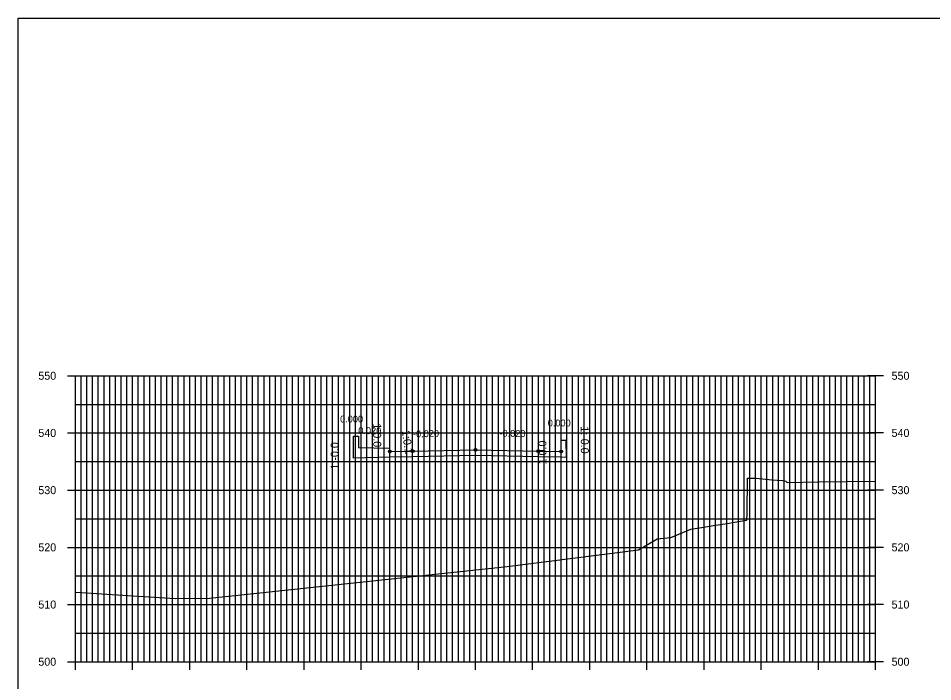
# Model space of a CAD drawing. Extents: x 1509063 to 1512863, y 401160 to 402918.
# Drawn here: x 1511102.7 to 1511262.7, y 402346.1 to 402462.1 of the extents above; entities that cross this region are included whole.
import ezdxf

# ---------------------------------------------------------------- set-up
doc = ezdxf.new("R2010")
doc.units = 0
for name, color, linetype in [('NBL1', 7, 'Continuous'), ('PET_P', 7, 'Continuous'), ('PRC', 7, 'Continuous'), ('PSP_P', 7, 'Continuous'), ('XAX_P', 7, 'Continuous'), ('XAXTIC_P', 7, 'Continuous'), ('XAXTXT_P_T', 7, 'Continuous'), ('XGL_P', 7, 'Continuous'), ('XSL1_P', 7, 'Continuous'), ('XSL1_P_T', 7, 'Continuous'), ('XSL3_P', 7, 'Continuous'), ('XSLOG', 7, 'Continuous')]:
    doc.layers.add(name, color=color, linetype=linetype)

msp = doc.modelspace()

# ---------------------------------------------------------------- linework, layer by layer
at = {"layer": 'NBL1'}
msp.add_lwpolyline([(1511422.73, 402252.08), (1511102.73, 402252.08), (1511102.73, 402462.08), (1511422.73, 402462.08)], close=True, dxfattribs=at)
at = {"layer": 'PET_P'}
for centre in [(1511171.73, 402386.4), (1511193.73, 402386.4)]:
    msp.add_circle(centre, 0.25, dxfattribs=at)
at = {"layer": 'PRC'}
msp.add_circle((1511182.73, 402386.62), 0.25, dxfattribs=at)
at = {"layer": 'PSP_P'}
for centre in [(1511167.73, 402386.32), (1511197.73, 402386.32)]:
    msp.add_circle(centre, 0.25, dxfattribs=at)
at = {"layer": 'XAX_P'}
for p, q in [((1511112.73, 402349.58), (1511112.73, 402399.58)), ((1511182.73, 402349.58), (1511182.73, 402399.58)), ((1511252.73, 402349.58), (1511252.73, 402399.58)), ((1511112.73, 402349.58), (1511252.73, 402349.58))]:
    msp.add_line(p, q, dxfattribs=at)
at = {"layer": 'XAXTIC_P'}
for p, q in [((1511111.33, 402399.58), (1511114.13, 402399.58)), ((1511181.33, 402399.58), (1511184.13, 402399.58)), ((1511254.13, 402399.58), (1511251.33, 402399.58)), ((1511111.33, 402389.58), (1511114.13, 402389.58)), ((1511181.33, 402389.58), (1511184.13, 402389.58)), ((1511254.13, 402389.58), (1511251.33, 402389.58)), ((1511111.33, 402379.58), (1511114.13, 402379.58)), ((1511181.33, 402379.58), (1511184.13, 402379.58)), ((1511254.13, 402379.58), (1511251.33, 402379.58)), ((1511111.33, 402369.58), (1511114.13, 402369.58)), ((1511181.33, 402369.58), (1511184.13, 402369.58)), ((1511254.13, 402369.58), (1511251.33, 402369.58)), ((1511111.33, 402359.58), (1511114.13, 402359.58)), ((1511181.33, 402359.58), (1511184.13, 402359.58)), ((1511254.13, 402359.58), (1511251.33, 402359.58)), ((1511112.73, 402348.18), (1511112.73, 402350.98)), ((1511122.73, 402348.18), (1511122.73, 402350.98)), ((1511132.73, 402348.18), (1511132.73, 402350.98)), ((1511142.73, 402348.18), (1511142.73, 402350.98)), ((1511152.73, 402348.18), (1511152.73, 402350.98)), ((1511162.73, 402348.18), (1511162.73, 402350.98)), ((1511172.73, 402348.18), (1511172.73, 402350.98)), ((1511182.73, 402348.18), (1511182.73, 402350.98)), ((1511192.73, 402348.18), (1511192.73, 402350.98)), ((1511202.73, 402348.18), (1511202.73, 402350.98)), ((1511212.73, 402348.18), (1511212.73, 402350.98)), ((1511222.73, 402348.18), (1511222.73, 402350.98)), ((1511232.73, 402348.18), (1511232.73, 402350.98)), ((1511242.73, 402348.18), (1511242.73, 402350.98)), ((1511252.73, 402348.18), (1511252.73, 402350.98)), ((1511111.33, 402349.58), (1511114.13, 402349.58)), ((1511181.33, 402349.58), (1511184.13, 402349.58)), ((1511254.13, 402349.58), (1511251.33, 402349.58))]:
    msp.add_line(p, q, dxfattribs=at)
at = {"layer": 'XGL_P'}
for p, q in [((1511112.73, 402399.58), (1511252.73, 402399.58)), ((1511112.73, 402349.58), (1511112.73, 402399.58)), ((1511113.73, 402349.58), (1511113.73, 402399.58)), ((1511114.73, 402349.58), (1511114.73, 402399.58)), ((1511115.73, 402349.58), (1511115.73, 402399.58)), ((1511116.73, 402349.58), (1511116.73, 402399.58)), ((1511117.73, 402349.58), (1511117.73, 402399.58)), ((1511118.73, 402349.58), (1511118.73, 402399.58)), ((1511119.73, 402349.58), (1511119.73, 402399.58)), ((1511120.73, 402349.58), (1511120.73, 402399.58)), ((1511121.73, 402349.58), (1511121.73, 402399.58)), ((1511122.73, 402349.58), (1511122.73, 402399.58)), ((1511123.73, 402349.58), (1511123.73, 402399.58)), ((1511124.73, 402349.58), (1511124.73, 402399.58)), ((1511125.73, 402349.58), (1511125.73, 402399.58)), ((1511126.73, 402349.58), (1511126.73, 402399.58)), ((1511127.73, 402349.58), (1511127.73, 402399.58)), ((1511128.73, 402349.58), (1511128.73, 402399.58)), ((1511129.73, 402349.58), (1511129.73, 402399.58)), ((1511130.73, 402349.58), (1511130.73, 402399.58)), ((1511131.73, 402349.58), (1511131.73, 402399.58)), ((1511132.73, 402349.58), (1511132.73, 402399.58)), ((1511133.73, 402349.58), (1511133.73, 402399.58)), ((1511134.73, 402349.58), (1511134.73, 402399.58)), ((1511135.73, 402349.58), (1511135.73, 402399.58)), ((1511136.73, 402349.58), (1511136.73, 402399.58)), ((1511137.73, 402349.58), (1511137.73, 402399.58)), ((1511138.73, 402349.58), (1511138.73, 402399.58)), ((1511139.73, 402349.58), (1511139.73, 402399.58)), ((1511140.73, 402349.58), (1511140.73, 402399.58)), ((1511141.73, 402349.58), (1511141.73, 402399.58)), ((1511142.73, 402349.58), (1511142.73, 402399.58)), ((1511143.73, 402349.58), (1511143.73, 402399.58)), ((1511144.73, 402349.58), (1511144.73, 402399.58)), ((1511145.73, 402349.58), (1511145.73, 402399.58)), ((1511146.73, 402349.58), (1511146.73, 402399.58)), ((1511147.73, 402349.58), (1511147.73, 402399.58)), ((1511148.73, 402349.58), (1511148.73, 402399.58)), ((1511149.73, 402349.58), (1511149.73, 402399.58)), ((1511150.73, 402349.58), (1511150.73, 402399.58)), ((1511151.73, 402349.58), (1511151.73, 402399.58)), ((1511152.73, 402349.58), (1511152.73, 402399.58)), ((1511153.73, 402349.58), (1511153.73, 402399.58)), ((1511154.73, 402349.58), (1511154.73, 402399.58)), ((1511155.73, 402349.58), (1511155.73, 402399.58)), ((1511156.73, 402349.58), (1511156.73, 402399.58)), ((1511157.73, 402349.58), (1511157.73, 402399.58)), ((1511158.73, 402349.58), (1511158.73, 402399.58)), ((1511159.73, 402349.58), (1511159.73, 402399.58)), ((1511160.73, 402349.58), (1511160.73, 402399.58)), ((1511161.73, 402349.58), (1511161.73, 402399.58)), ((1511162.73, 402349.58), (1511162.73, 402399.58)), ((1511163.73, 402349.58), (1511163.73, 402399.58)), ((1511164.73, 402349.58), (1511164.73, 402399.58)), ((1511165.73, 402349.58), (1511165.73, 402399.58)), ((1511166.73, 402349.58), (1511166.73, 402399.58)), ((1511167.73, 402349.58), (1511167.73, 402399.58)), ((1511168.73, 402349.58), (1511168.73, 402399.58)), ((1511169.73, 402349.58), (1511169.73, 402399.58)), ((1511170.73, 402349.58), (1511170.73, 402399.58)), ((1511171.73, 402349.58), (1511171.73, 402399.58)), ((1511172.73, 402349.58), (1511172.73, 402399.58)), ((1511173.73, 402349.58), (1511173.73, 402399.58)), ((1511174.73, 402349.58), (1511174.73, 402399.58)), ((1511175.73, 402349.58), (1511175.73, 402399.58)), ((1511176.73, 402349.58), (1511176.73, 402399.58)), ((1511177.73, 402349.58), (1511177.73, 402399.58)), ((1511178.73, 402349.58), (1511178.73, 402399.58)), ((1511179.73, 402349.58), (1511179.73, 402399.58)), ((1511180.73, 402349.58), (1511180.73, 402399.58)), ((1511181.73, 402349.58), (1511181.73, 402399.58)), ((1511182.73, 402349.58), (1511182.73, 402399.58)), ((1511183.73, 402349.58), (1511183.73, 402399.58)), ((1511184.73, 402349.58), (1511184.73, 402399.58)), ((1511185.73, 402349.58), (1511185.73, 402399.58)), ((1511186.73, 402349.58), (1511186.73, 402399.58)), ((1511187.73, 402349.58), (1511187.73, 402399.58)), ((1511188.73, 402349.58), (1511188.73, 402399.58)), ((1511189.73, 402349.58), (1511189.73, 402399.58)), ((1511190.73, 402349.58), (1511190.73, 402399.58)), ((1511191.73, 402349.58), (1511191.73, 402399.58)), ((1511192.73, 402349.58), (1511192.73, 402399.58)), ((1511193.73, 402349.58), (1511193.73, 402399.58)), ((1511194.73, 402349.58), (1511194.73, 402399.58)), ((1511195.73, 402349.58), (1511195.73, 402399.58)), ((1511196.73, 402349.58), (1511196.73, 402399.58)), ((1511197.73, 402349.58), (1511197.73, 402399.58)), ((1511198.73, 402349.58), (1511198.73, 402399.58)), ((1511199.73, 402349.58), (1511199.73, 402399.58)), ((1511200.73, 402349.58), (1511200.73, 402399.58)), ((1511201.73, 402349.58), (1511201.73, 402399.58)), ((1511202.73, 402349.58), (1511202.73, 402399.58)), ((1511203.73, 402349.58), (1511203.73, 402399.58)), ((1511204.73, 402349.58), (1511204.73, 402399.58)), ((1511205.73, 402349.58), (1511205.73, 402399.58)), ((1511206.73, 402349.58), (1511206.73, 402399.58)), ((1511207.73, 402349.58), (1511207.73, 402399.58)), ((1511208.73, 402349.58), (1511208.73, 402399.58)), ((1511209.73, 402349.58), (1511209.73, 402399.58)), ((1511210.73, 402349.58), (1511210.73, 402399.58)), ((1511211.73, 402349.58), (1511211.73, 402399.58)), ((1511212.73, 402349.58), (1511212.73, 402399.58)), ((1511213.73, 402349.58), (1511213.73, 402399.58)), ((1511214.73, 402349.58), (1511214.73, 402399.58)), ((1511215.73, 402349.58), (1511215.73, 402399.58)), ((1511216.73, 402349.58), (1511216.73, 402399.58)), ((1511217.73, 402349.58), (1511217.73, 402399.58)), ((1511218.73, 402349.58), (1511218.73, 402399.58)), ((1511219.73, 402349.58), (1511219.73, 402399.58)), ((1511220.73, 402349.58), (1511220.73, 402399.58)), ((1511221.73, 402349.58), (1511221.73, 402399.58)), ((1511222.73, 402349.58), (1511222.73, 402399.58)), ((1511223.73, 402349.58), (1511223.73, 402399.58)), ((1511224.73, 402349.58), (1511224.73, 402399.58)), ((1511225.73, 402349.58), (1511225.73, 402399.58)), ((1511226.73, 402349.58), (1511226.73, 402399.58)), ((1511227.73, 402349.58), (1511227.73, 402399.58)), ((1511228.73, 402349.58), (1511228.73, 402399.58)), ((1511229.73, 402349.58), (1511229.73, 402399.58)), ((1511230.73, 402349.58), (1511230.73, 402399.58)), ((1511231.73, 402349.58), (1511231.73, 402399.58)), ((1511232.73, 402349.58), (1511232.73, 402399.58)), ((1511233.73, 402349.58), (1511233.73, 402399.58)), ((1511234.73, 402349.58), (1511234.73, 402399.58)), ((1511235.73, 402349.58), (1511235.73, 402399.58)), ((1511236.73, 402349.58), (1511236.73, 402399.58)), ((1511237.73, 402349.58), (1511237.73, 402399.58)), ((1511238.73, 402349.58), (1511238.73, 402399.58)), ((1511239.73, 402349.58), (1511239.73, 402399.58)), ((1511240.73, 402349.58), (1511240.73, 402399.58)), ((1511241.73, 402349.58), (1511241.73, 402399.58)), ((1511242.73, 402349.58), (1511242.73, 402399.58)), ((1511243.73, 402349.58), (1511243.73, 402399.58)), ((1511244.73, 402349.58), (1511244.73, 402399.58)), ((1511245.73, 402349.58), (1511245.73, 402399.58)), ((1511246.73, 402349.58), (1511246.73, 402399.58)), ((1511247.73, 402349.58), (1511247.73, 402399.58)), ((1511248.73, 402349.58), (1511248.73, 402399.58)), ((1511249.73, 402349.58), (1511249.73, 402399.58)), ((1511250.73, 402349.58), (1511250.73, 402399.58)), ((1511251.73, 402349.58), (1511251.73, 402399.58)), ((1511252.73, 402349.58), (1511252.73, 402399.58)), ((1511112.73, 402394.58), (1511252.73, 402394.58)), ((1511112.73, 402389.58), (1511252.73, 402389.58)), ((1511112.73, 402384.58), (1511252.73, 402384.58)), ((1511112.73, 402379.58), (1511252.73, 402379.58)), ((1511112.73, 402374.58), (1511252.73, 402374.58)), ((1511112.73, 402369.58), (1511252.73, 402369.58)), ((1511112.73, 402364.58), (1511252.73, 402364.58)), ((1511112.73, 402359.58), (1511252.73, 402359.58)), ((1511112.73, 402354.58), (1511252.73, 402354.58)), ((1511112.73, 402349.58), (1511252.73, 402349.58))]:
    msp.add_line(p, q, dxfattribs=at)
at = {"layer": 'XSL1_P'}
msp.add_lwpolyline([(1511161.39, 402385.19), (1511161.4, 402389.01), (1511162.23, 402389.01), (1511162.23, 402387.01), (1511167.65, 402386.9), (1511167.73, 402386.32), (1511171.73, 402386.4), (1511182.73, 402386.62), (1511193.73, 402386.4), (1511197.73, 402386.32), (1511197.73, 402388.32), (1511198.56, 402388.32), (1511198.57, 402385.3)], dxfattribs=at)
at = {"layer": 'XSL3_P'}
msp.add_lwpolyline([(1511171.73, 402385.4), (1511167.73, 402385.32), (1511161.39, 402385.19), (1511161.4, 402389.01), (1511162.23, 402389.01), (1511162.23, 402387.01), (1511167.65, 402386.9), (1511167.73, 402386.32), (1511171.73, 402386.4), (1511182.73, 402386.62), (1511193.73, 402386.4), (1511197.73, 402386.32), (1511197.73, 402388.32), (1511198.56, 402388.32), (1511198.57, 402385.3), (1511197.73, 402385.32), (1511193.73, 402385.4), (1511182.73, 402385.62)], close=True, dxfattribs=at)
at = {"layer": 'XSLOG'}
msp.add_lwpolyline([(1511112.73, 402361.74), (1511130.19, 402360.66), (1511136.16, 402360.69), (1511141.73, 402361.25), (1511188.27, 402366.25), (1511211.23, 402369.12), (1511214.49, 402371.04), (1511216.92, 402371.33), (1511220.42, 402372.76), (1511222.29, 402373.06), (1511224.39, 402373.39), (1511226.76, 402373.77), (1511229.46, 402374.2), (1511230.22, 402374.32), (1511230.25, 402375.55), (1511230.35, 402381.67), (1511230.87, 402381.67), (1511231.43, 402381.68), (1511231.83, 402381.65), (1511234.59, 402381.39), (1511236.42, 402381.24), (1511236.78, 402381.2), (1511237, 402381.16), (1511237.02, 402381.14), (1511237.24, 402380.93), (1511242.71, 402381.01), (1511252.73, 402381.15)], dxfattribs=at)

# ---------------------------------------------------------------- texts
at = {"layer": 'XAXTXT_P_T'}
for s, p in [('550', (1511106.24, 402398.88)), ('550', (1511255.53, 402398.88)), ('540', (1511106.24, 402388.88)), ('540', (1511255.53, 402388.88)), ('530', (1511106.24, 402378.88)), ('530', (1511255.53, 402378.88)), ('520', (1511106.24, 402368.88)), ('520', (1511255.53, 402368.88)), ('510', (1511106.24, 402358.88)), ('510', (1511255.53, 402358.88)), ('500', (1511106.24, 402348.88)), ('500', (1511255.53, 402348.88))]:
    msp.add_text(s, height=1.4, dxfattribs=at).set_placement(p)
at = {"layer": 'XSL1_P_T'}
for s, height, rotation, p in [('0.000', 1.2, 360, (1511159.04, 402391.41)), ('0.000', 1.2, 360, (1511159.04, 402391.41)), ('0.020', 1.2, 358.8542, (1511162.21, 402389.41)), ('0.020', 1.2, 358.8542, (1511162.21, 402389.41)), ('1:0.0', 1.4, 270.0286, (1511164.83, 402391.25)), ('1:0.0', 1.4, 270.0286, (1511164.83, 402391.25)), ('0.000', 1.2, 360, (1511195.37, 402390.72)), ('0.000', 1.2, 360, (1511195.37, 402390.72)), ('1:-0.0', 1.4, 270.1899, (1511201.15, 402390.75)), ('1:-0.0', 1.4, 270.1899, (1511201.15, 402390.75)), ('1:0.1', 1.4, 278.1301, (1511169.83, 402389.96)), ('1:0.1', 1.4, 278.1301, (1511169.83, 402389.96)), ('-0.020', 1.2, 1.1458, (1511171.81, 402388.8)), ('-0.020', 1.2, 1.1458, (1511171.81, 402388.8)), ('-0.020', 1.2, 1.1458, (1511171.81, 402388.8)), ('-0.020', 1.2, 358.8542, (1511186.91, 402388.94)), ('-0.020', 1.2, 358.8542, (1511186.91, 402388.94)), ('-0.020', 1.2, 358.8542, (1511186.91, 402388.94)), ('1:-0.0', 1.4, 89.85, (1511158.78, 402383.18)), ('1:-0.0', 1.4, 89.85, (1511158.78, 402383.18)), ('1:0.0', 1.4, 89.9714, (1511195.13, 402384.08)), ('1:0.0', 1.4, 89.9714, (1511195.13, 402384.08))]:
    msp.add_text(s, height=height, rotation=rotation, dxfattribs=at).set_placement(p)

doc.saveas('drawing.dxf')
